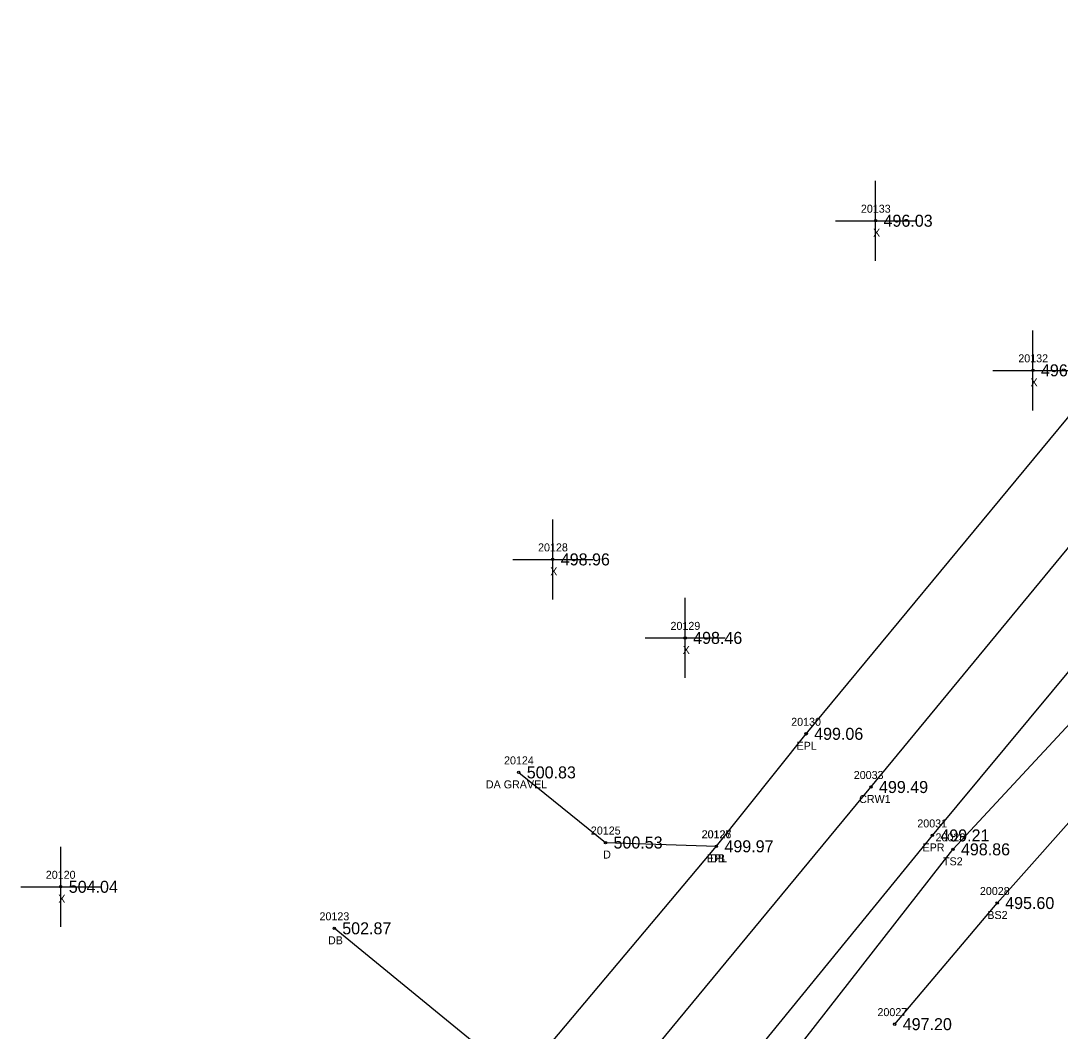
# Model space of a CAD drawing. Extents: x 1649406 to 1650436, y 896752 to 898178.
# Drawn here: x 1649451.3 to 1649581.2, y 896879.4 to 897005.7 of the extents above; entities that cross this region are included whole.
import ezdxf

# ---------------------------------------------------------------- set-up
doc = ezdxf.new("R2010")
doc.units = 0
for name, color, linetype in [('RD_DTM_BkLn1', 7, 'Continuous'), ('RD_DTM_BkLn2', 7, 'Continuous'), ('RD_DTM_BkLn_txCode', 7, 'Continuous'), ('RD_EX_Driveway', 7, 'Continuous'), ('RD_EX_Driveway_txCode', 7, 'Continuous'), ('RD_EX_Misc', 7, 'Continuous'), ('RD_EX_Misc_txCode', 7, 'Continuous'), ('RD_EX_Road', 7, 'Continuous'), ('RD_EX_Road_txCode', 7, 'Continuous'), ('RD_EX_TX_Driveway_ELEV', 7, 'Continuous'), ('RD_EX_TX_Misc_ELEV', 7, 'Continuous'), ('RD_EX_TX_Road_ELEV', 7, 'Continuous'), ('RD_HC_Survey_ELEV', 7, 'Continuous'), ('RD_HC_Survey_txCode', 7, 'Continuous'), ('RD_SMD_Locator', 7, 'Continuous')]:
    doc.layers.add(name, color=color, linetype=linetype)

msp = doc.modelspace()

# ---------------------------------------------------------------- linework, layer by layer
at = {"layer": 'RD_DTM_BkLn1'}
msp.add_lwpolyline([(1649466.79, 896799.14), (1649494.97, 896834.25), (1649557.53, 896909.97), (1649590.88, 896950.41), (1649622.36, 896988.16), (1649622.36, 896988.48), (1649654.33, 897027.92), (1649685.38, 897067.52), (1649715.96, 897107.48), (1649743.64, 897146.32), (1649771.01, 897187.23), (1649797.64, 897230.08), (1649820.89, 897273.98), (1649842.91, 897321.22), (1649862.74, 897368.05), (1649877.08, 897408.66)], dxfattribs=at)
at = {"layer": 'RD_DTM_BkLn2'}
for points in [[(1649477.28, 896790.29), (1649506.04, 896824.84), (1649536.41, 896861.97), (1649567.77, 896902.18), (1649602.54, 896939.62), (1649634.46, 896978.81), (1649648.91, 896984.68)], [(1649560.5, 896880.33), (1649573.3, 896895.47), (1649608.49, 896935.06), (1649639.66, 896968.36)]]:
    msp.add_lwpolyline(points, dxfattribs=at)
at = {"layer": 'RD_EX_Driveway'}
msp.add_line((1649513.65, 896873.34), (1649490.46, 896892.31), dxfattribs=at)
msp.add_lwpolyline([(1649513.52, 896911.8), (1649524.36, 896903.03), (1649538.22, 896902.56)], dxfattribs=at)
at = {"layer": 'RD_EX_Misc'}
for p, q in [((1649558.1, 896975.75), (1649558.1, 896985.75)), ((1649553.1, 896980.75), (1649563.1, 896980.75)), ((1649577.77, 896957.05), (1649577.77, 896967.05)), ((1649572.77, 896962.05), (1649582.77, 896962.05)), ((1649517.77, 896933.42), (1649517.77, 896943.42)), ((1649512.77, 896938.42), (1649522.77, 896938.42)), ((1649534.31, 896923.61), (1649534.31, 896933.61)), ((1649529.31, 896928.61), (1649539.31, 896928.61)), ((1649456.29, 896892.5), (1649456.29, 896902.5)), ((1649451.29, 896897.5), (1649461.29, 896897.5))]:
    msp.add_line(p, q, dxfattribs=at)
at = {"layer": 'RD_EX_Road'}
for points in [[(1649459.38, 896805.71), (1649486.55, 896839.62), (1649513.65, 896873.34), (1649538.22, 896902.56), (1649549.43, 896916.62), (1649583.1, 896957.27), (1649614.8, 896995.02), (1649647.06, 897035.69), (1649677.62, 897074.51), (1649708.33, 897114.44), (1649735.5, 897151.61), (1649762.11, 897192.19), (1649788.21, 897235.29), (1649812.17, 897279.73), (1649834.32, 897326.54), (1649852.94, 897371.82), (1649867.51, 897411.96)], [(1649474.75, 896792.65), (1649502.78, 896827.35), (1649565.2, 896903.92), (1649598.28, 896943.71), (1649629.8, 896982.26), (1649667.92, 897029.33), (1649693.13, 897061.44), (1649723.58, 897101.84), (1649752.37, 897141.09), (1649779.72, 897182.3), (1649806.12, 897225.84), (1649830.13, 897270.79), (1649852.39, 897317.43), (1649871.98, 897364.35), (1649886.55, 897406.09)]]:
    msp.add_lwpolyline(points, dxfattribs=at)
at = {"layer": 'RD_SMD_Locator'}
for centre in [(1649558.1, 896980.75), (1649577.77, 896962.05), (1649517.77, 896938.42), (1649534.31, 896928.61), (1649549.43, 896916.62), (1649513.52, 896911.8), (1649557.53, 896909.97), (1649524.36, 896903.03), (1649565.2, 896903.92), (1649538.22, 896902.56), (1649538.22, 896902.56), (1649567.77, 896902.18), (1649456.29, 896897.5), (1649573.3, 896895.47), (1649490.46, 896892.31), (1649560.5, 896880.33)]:
    msp.add_circle(centre, 0.15, dxfattribs=at)

# ---------------------------------------------------------------- texts
at = {"layer": 'RD_DTM_BkLn_txCode'}
for s, p in [('20026', (1649565.59, 896903.18)), ('TS2', (1649566.53, 896900.18)), ('20028', (1649571.14, 896896.47)), ('BS2', (1649572.07, 896893.47)), ('20027', (1649558.34, 896881.33))]:
    msp.add_text(s, height=1, dxfattribs=at).set_placement(p)
at = {"layer": 'RD_EX_Driveway_txCode'}
for s, p in [('20124', (1649511.68, 896912.8)), ('DA GRAVEL', (1649509.41, 896909.8)), ('20125', (1649522.53, 896904.03)), ('20126', (1649536.36, 896903.56)), ('D', (1649524.06, 896901.03)), ('DB', (1649537.44, 896900.56)), ('20123', (1649488.62, 896893.31)), ('DB', (1649489.68, 896890.31))]:
    msp.add_text(s, height=1, dxfattribs=at).set_placement(p)
at = {"layer": 'RD_EX_Misc_txCode'}
for s, p in [('20133', (1649556.27, 896981.75)), ('X', (1649557.79, 896978.75)), ('20132', (1649575.94, 896963.05)), ('X', (1649577.46, 896960.05)), ('20128', (1649515.93, 896939.42)), ('X', (1649517.45, 896936.42)), ('20129', (1649532.48, 896929.61)), ('X', (1649534, 896926.61)), ('20120', (1649454.42, 896898.5)), ('X', (1649455.98, 896895.5))]:
    msp.add_text(s, height=1, dxfattribs=at).set_placement(p)
at = {"layer": 'RD_EX_Road_txCode'}
for s, p in [('20130', (1649547.56, 896917.62)), ('EPL', (1649548.23, 896914.62)), ('20031', (1649563.32, 896904.92)), ('20127', (1649536.39, 896903.56)), ('EPR', (1649563.97, 896901.92)), ('EPL', (1649537.02, 896900.56))]:
    msp.add_text(s, height=1, dxfattribs=at).set_placement(p)
at = {"layer": 'RD_EX_TX_Driveway_ELEV'}
for s, p in [('500.83', (1649514.52, 896911.05)), ('500.53', (1649525.36, 896902.28)), ('499.97', (1649539.22, 896901.81)), ('502.87', (1649491.46, 896891.56))]:
    msp.add_text(s, height=1.5, dxfattribs=at).set_placement(p)
at = {"layer": 'RD_EX_TX_Misc_ELEV'}
for s, p in [('496.03', (1649559.1, 896980)), ('496.04', (1649578.77, 896961.3)), ('498.96', (1649518.77, 896937.67)), ('498.46', (1649535.31, 896927.86)), ('498.86', (1649568.77, 896901.43)), ('504.04', (1649457.29, 896896.75)), ('495.60', (1649574.3, 896894.72)), ('497.20', (1649561.5, 896879.58))]:
    msp.add_text(s, height=1.5, dxfattribs=at).set_placement(p)
at = {"layer": 'RD_EX_TX_Road_ELEV'}
for s, p in [('499.06', (1649550.43, 896915.87)), ('499.21', (1649566.2, 896903.17)), ('499.97', (1649539.22, 896901.81))]:
    msp.add_text(s, height=1.5, dxfattribs=at).set_placement(p)
at = {"layer": 'RD_HC_Survey_ELEV'}
msp.add_text('499.49', height=1.5, dxfattribs=at).set_placement((1649558.53, 896909.22))
at = {"layer": 'RD_HC_Survey_txCode'}
for s, p in [('20033', (1649555.38, 896910.97)), ('CRW1', (1649556.05, 896907.97))]:
    msp.add_text(s, height=1, dxfattribs=at).set_placement(p)

doc.saveas('drawing.dxf')
